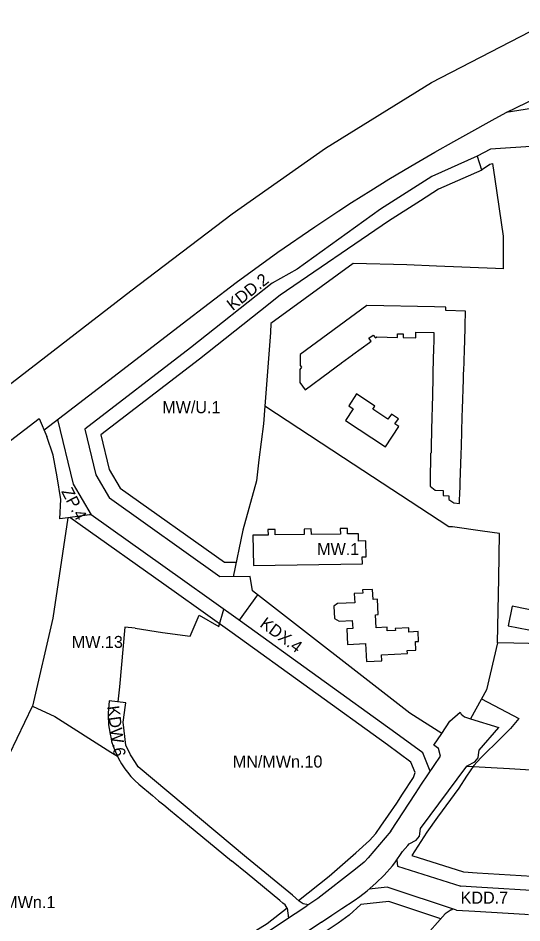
# Model space of a CAD drawing. Extents: x 7427074 to 7428708, y 5545888 to 5547145.
# Drawn here: x 7427353.4 to 7427562.4, y 5546349.6 to 5546725 of the extents above; entities that cross this region are included whole.
import ezdxf

# ---------------------------------------------------------------- set-up
doc = ezdxf.new("R2010")
doc.units = 0
for name, color, linetype in [('linie_rozgraniczajace', 7, 'Continuous'), ('linie_zabudowy_nieprzekraczalne', 7, 'Continuous'), ('linie_zabudowy_obowiazujace', 7, 'Continuous'), ('oznaczenia_przeznaczen', 7, 'Continuous')]:
    doc.layers.add(name, color=color, linetype=linetype)

msp = doc.modelspace()

# ---------------------------------------------------------------- linework, layer by layer
at = {"layer": 'linie_rozgraniczajace'}
for p, q in [((7427245.64, 5546492.63), (7427400.2, 5546611.86)), ((7427362.2, 5546558.93), (7427365.35, 5546551.44)), ((7427369.81, 5546558.47), (7427376.26, 5546531.66)), ((7427367.91, 5546543.69), (7427365.35, 5546551.44)), ((7427385.64, 5546535.45), (7427391.29, 5546525.85)), ((7427376.26, 5546531.66), (7427383.75, 5546518.94)), ((7427437.14, 5546493.18), (7427391.29, 5546525.85)), ((7427421.58, 5546491.99), (7427383.75, 5546518.94)), ((7427445.72, 5546474.79), (7427421.58, 5546491.99)), ((7427452.66, 5546485.74), (7427445.15, 5546475.2)), ((7427436.65, 5546472.62), (7427438.79, 5546479.73)), ((7427547.71, 5546446.24), (7427541.02, 5546434.22)), ((7427391.87, 5546420.47), (7427394.65, 5546418.71)), ((7427539.52, 5546414.55), (7427557.29, 5546413.6)), ((7427510.46, 5546375.65), (7427510.8, 5546373.1)), ((7427510.8, 5546373.1), (7427537.12, 5546364.79)), ((7427506.51, 5546364.47), (7427498.99, 5546363.62)), ((7427535.29, 5546354.89), (7427506.51, 5546364.47)), ((7427533.07, 5546355.02), (7427533.68, 5546355.42))]:
    msp.add_line(p, q, dxfattribs=at)
for points in [[(7427400.2, 5546611.86), (7427442.19, 5546643.82), (7427480.94, 5546671.03), (7427524.86, 5546698.24), (7427615.03, 5546744.99), (7427747.54, 5546812.47), (7427897.12, 5546887.45), (7428084.42, 5546980.69), (7428179.45, 5547028.08)], [(7427364.2, 5546554.17), (7427395.05, 5546577.83), (7427421.52, 5546598.13), (7427443.89, 5546615.25), (7427461.19, 5546627.88), (7427476.45, 5546638.44), (7427486.49, 5546645.1), (7427491.66, 5546648.44), (7427499.68, 5546653.51), (7427507.23, 5546658.17), (7427516.35, 5546663.63), (7427526.34, 5546669.42), (7427534.09, 5546673.78), (7427540.36, 5546677.22), (7427550.02, 5546682.6), (7427555.89, 5546685.9), (7427594.96, 5546704.86), (7427638.36, 5546720.62)], [(7427655.48, 5546683.03), (7427641.71, 5546683.78), (7427625.07, 5546685.04), (7427596.01, 5546686.32), (7427586.83, 5546686.79), (7427569.02, 5546687.86), (7427555.86, 5546685.88)], [(7427670.02, 5546665.3), (7427656.69, 5546667.04), (7427641.81, 5546667.88), (7427623.85, 5546668.9), (7427585.97, 5546670.99), (7427568.18, 5546671.93), (7427549.37, 5546670.57), (7427543.89, 5546667.66), (7427525, 5546659.31), (7427503.72, 5546645.77), (7427469.2, 5546620.79), (7427458.78, 5546615.05), (7427424.98, 5546588.18), (7427381.06, 5546554.49)], [(7427543.89, 5546667.66), (7427545.7, 5546661.99), (7427549.06, 5546664.43), (7427550.23, 5546664.64), (7427551.17, 5546658.23), (7427554.64, 5546634.49), (7427554.66, 5546620.99), (7427551.42, 5546621.12), (7427526.94, 5546622.11), (7427514.73, 5546622.57), (7427492.47, 5546623.2), (7427472.43, 5546608.61), (7427458.25, 5546598.27), (7427458.14, 5546594.5), (7427455.74, 5546564.02)], [(7427552.3, 5546465.76), (7427552.8, 5546492.67), (7427553.14, 5546511.14), (7427546.01, 5546512.12), (7427533.67, 5546513.88), (7427532.08, 5546513.86), (7427488.33, 5546542.61), (7427455.74, 5546564.02), (7427455.16, 5546556.61), (7427453.34, 5546541.67), (7427452.3, 5546532.98)], [(7427202.76, 5546436.65), (7427362.2, 5546558.93)], [(7427381.06, 5546554.49), (7427385.64, 5546535.45)], [(7427374, 5546517.72), (7427370.69, 5546517.27), (7427371.12, 5546525.28), (7427369.63, 5546534.69), (7427367.91, 5546543.69)], [(7427452.3, 5546532.98), (7427446.7, 5546512.58), (7427442.65, 5546493.23)], [(7427374, 5546517.72), (7427367.84, 5546476.07), (7427359.35, 5546439.56)], [(7427383.75, 5546518.94), (7427382.98, 5546518.97), (7427374, 5546517.72)], [(7427529.12, 5546428.2), (7427515.88, 5546436.56), (7427450.6, 5546487.35), (7427449.63, 5546493.29), (7427437.14, 5546493.18)], [(7427401.93, 5546471.81), (7427413.29, 5546470.12), (7427424.76, 5546468.55), (7427428.56, 5546477.33), (7427436.65, 5546472.62)], [(7427524.4, 5546412.55), (7427521.25, 5546420.11), (7427510.14, 5546428.36), (7427445.72, 5546474.79)], [(7427401.93, 5546471.81), (7427397.76, 5546472.31), (7427395.44, 5546447.54), (7427394.79, 5546441.29)], [(7427571.25, 5546465.36), (7427558.99, 5546465.62), (7427552.3, 5546465.76), (7427547.71, 5546446.24)], [(7427346.74, 5546412.98), (7427359.35, 5546439.56)], [(7427359.35, 5546439.56), (7427368.72, 5546435.2), (7427391.87, 5546420.47)], [(7427473.91, 5546357.13), (7427471.62, 5546357.48), (7427470.07, 5546358.66), (7427467.2, 5546361.06), (7427448.12, 5546376.67), (7427403.29, 5546414.31), (7427402.06, 5546416.09), (7427399.99, 5546419.3), (7427398.11, 5546423.3), (7427397.05, 5546432.84), (7427397.97, 5546439.96), (7427398.11, 5546440.94), (7427391.2, 5546441.66), (7427390.81, 5546436.61), (7427390.81, 5546434.76), (7427390.9, 5546432.78), (7427390.99, 5546431.77), (7427391.15, 5546430.3), (7427391.55, 5546427.84), (7427391.99, 5546425.97), (7427392.23, 5546424.91), (7427392.87, 5546422.98), (7427393.82, 5546420.51), (7427395.08, 5546417.78), (7427396.36, 5546415.65), (7427397.71, 5546413.56), (7427398.76, 5546412.13), (7427400.24, 5546410.37), (7427401.81, 5546408.68), (7427403.48, 5546407.09), (7427405.13, 5546405.71), (7427407.48, 5546403.76), (7427409.11, 5546402.39), (7427411.65, 5546400.27), (7427413.9, 5546398.52), (7427416.68, 5546396.21), (7427421.32, 5546392.37), (7427423.74, 5546390.48), (7427441.92, 5546375.34)], [(7427508.07, 5546387.66), (7427518.26, 5546403.28), (7427520.79, 5546407.15), (7427528.57, 5546418.77), (7427527.79, 5546421.99), (7427525.86, 5546423.31), (7427529.12, 5546428.2), (7427532.56, 5546433.34), (7427536.76, 5546437.06), (7427537.26, 5546436.2), (7427538.61, 5546435.05), (7427541.02, 5546434.22), (7427552.88, 5546430.65)], [(7427479.26, 5546349.84), (7427483.58, 5546352.73), (7427487.77, 5546355.52), (7427492.82, 5546358.9), (7427495.14, 5546360.55), (7427498.22, 5546362.95), (7427501.78, 5546366.05), (7427505.2, 5546369.35), (7427508.71, 5546373.21), (7427509.7, 5546374.51), (7427512.82, 5546379.21), (7427515.11, 5546381.76), (7427515.6, 5546382.42), (7427518.55, 5546383.91), (7427519.86, 5546385.58), (7427520.33, 5546388.79), (7427539.52, 5546414.55), (7427539.67, 5546414.74), (7427542.87, 5546416.35), (7427544.22, 5546418.08), (7427544.4, 5546419.3), (7427544.68, 5546421.22), (7427552.88, 5546430.65)], [(7427557.29, 5546413.6), (7427568.29, 5546413.01), (7427576.26, 5546387.77)], [(7427508.07, 5546387.66), (7427498.56, 5546376.59), (7427497.07, 5546374.91), (7427496.93, 5546374.74), (7427493.38, 5546371.94), (7427477.78, 5546359.68), (7427473.12, 5546356.61)], [(7427465.07, 5546355.74), (7427464.67, 5546356.41), (7427464.16, 5546357.01), (7427463.29, 5546357.8), (7427461.95, 5546358.91), (7427448.41, 5546370.12), (7427441.92, 5546375.34)], [(7427585.66, 5546361.85), (7427570.85, 5546362.75), (7427543.53, 5546364.4), (7427537.12, 5546364.79)], [(7427337.22, 5546278.25), (7427357.81, 5546290.12), (7427362.65, 5546292.17), (7427367.93, 5546295.03), (7427371.59, 5546297.02), (7427376.72, 5546299.98), (7427389.23, 5546307.22), (7427411.07, 5546319.08), (7427416.4, 5546321.96), (7427416.99, 5546320.6), (7427421.81, 5546323.13), (7427428.21, 5546326.84), (7427431.47, 5546329), (7427434.68, 5546331.13), (7427468.39, 5546353.49), (7427473.12, 5546356.61)], [(7427465.07, 5546355.74), (7427465.52, 5546351.58)], [(7427533.07, 5546355.02), (7427530.57, 5546353.37), (7427524.16, 5546346.19), (7427522.69, 5546344.23), (7427520.72, 5546340.78), (7427518.78, 5546337.59), (7427516.03, 5546333.03), (7427513.63, 5546329.06), (7427512.52, 5546326.87), (7427512.14, 5546326.11), (7427511.99, 5546325.8), (7427507.15, 5546316.17), (7427498.79, 5546300.65), (7427495.71, 5546294.66), (7427491.99, 5546288.77), (7427487.56, 5546281.59), (7427485.5, 5546278.63), (7427480.53, 5546273.21), (7427478.17, 5546270.58), (7427477.6, 5546269.37)], [(7427535.29, 5546354.89), (7427542.92, 5546354.42), (7427563.55, 5546353.18), (7427565.07, 5546353.09)], [(7427479.26, 5546349.84), (7427467.13, 5546341.73), (7427458.44, 5546335.98), (7427442.11, 5546325.17), (7427425.1, 5546314.77), (7427419.81, 5546311.95), (7427414.6, 5546309.15), (7427402.89, 5546302.98), (7427380.2, 5546291.01), (7427369.27, 5546285.25), (7427354.06, 5546276.83), (7427340.36, 5546269.25), (7427329.45, 5546262.24), (7427324.29, 5546258.02), (7427314.5, 5546248.22), (7427302.27, 5546235.33)]]:
    msp.add_lwpolyline(points, dxfattribs=at)
at = {"layer": 'linie_zabudowy_nieprzekraczalne'}
for p, q in [((7427545.65, 5546442.54), (7427561.18, 5546434.41)), ((7427517.43, 5546409.94), (7427518.11, 5546412.05)), ((7427507.21, 5546358.51), (7427495.65, 5546357.21)), ((7427528.75, 5546351.33), (7427507.21, 5546358.51))]:
    msp.add_line(p, q, dxfattribs=at)
for points in [[(7427545.72, 5546661.91), (7427527.84, 5546654.01), (7427520.37, 5546649.25)], [(7427520.37, 5546649.25), (7427507.09, 5546640.8), (7427462.12, 5546610.04), (7427454.02, 5546603.6)], [(7427387.8, 5546552.1), (7427391.26, 5546537.72), (7427395.81, 5546529.99), (7427439.04, 5546499.2), (7427443.91, 5546499.24)], [(7427518.11, 5546412.05), (7427516.35, 5546416.28), (7427506.59, 5546423.52), (7427442.23, 5546469.92), (7427418.1, 5546487.1), (7427374.94, 5546517.85)], [(7427561.18, 5546434.41), (7427557.61, 5546430.3), (7427553.76, 5546426.43), (7427545.39, 5546418.04), (7427542.51, 5546414.93), (7427539.47, 5546410.51), (7427536.21, 5546405.47), (7427527.39, 5546393.51), (7427522.96, 5546387.21), (7427516.68, 5546377.54), (7427538.22, 5546370.74), (7427543.89, 5546370.39), (7427571.22, 5546368.74), (7427586.1, 5546367.84), (7427620.52, 5546364.9)], [(7427499.2, 5546383.71), (7427501.75, 5546386.74), (7427503.82, 5546389.69), (7427507.1, 5546394.26), (7427510.56, 5546399.25), (7427512.91, 5546402.93), (7427517.43, 5546409.94)], [(7427469.76, 5546358.91), (7427482.44, 5546368.99), (7427493.51, 5546378.63), (7427499.2, 5546383.71)], [(7427495.65, 5546357.21), (7427490.69, 5546352.83), (7427486.19, 5546349.49), (7427480.4, 5546345.55), (7427466.21, 5546335.53), (7427452.71, 5546325.77), (7427445.38, 5546321.77), (7427439.81, 5546318.7), (7427418.08, 5546306.01), (7427404.24, 5546299.5), (7427392.77, 5546293.83), (7427373.57, 5546284.17), (7427366.91, 5546280.83), (7427354.99, 5546274.14)], [(7427257.14, 5546195.43), (7427285.02, 5546234.34), (7427290.57, 5546240.98), (7427293.76, 5546244.92), (7427305.32, 5546258.92), (7427313.52, 5546269.3), (7427316.86, 5546272.22), (7427340.92, 5546285.7), (7427355.54, 5546293.85), (7427357.88, 5546295.45), (7427365.28, 5546299.95), (7427382.65, 5546309.18), (7427384.23, 5546310.01), (7427404.8, 5546319.28), (7427408.61, 5546321.5), (7427431.21, 5546333.63), (7427456.78, 5546349.28), (7427464.99, 5546355.87)]]:
    msp.add_lwpolyline(points, dxfattribs=at)
at = {"layer": 'linie_zabudowy_obowiazujace'}
for points in [[(7427526.16, 5546605.2), (7427498.01, 5546605.73), (7427470.47, 5546585.4), (7427470.39, 5546580.9), (7427471.03, 5546580.24), (7427470.35, 5546579.23), (7427470.25, 5546573.8), (7427472.48, 5546570.79), (7427482.57, 5546578.24), (7427482.77, 5546578.39), (7427487.4, 5546581.81), (7427487.6, 5546581.95), (7427492.09, 5546585.27), (7427492.29, 5546585.42), (7427499.13, 5546590.47), (7427499.33, 5546590.61), (7427499.81, 5546590.97), (7427498.92, 5546592.18), (7427500.73, 5546593.51), (7427501.62, 5546592.31), (7427502.23, 5546592.74), (7427510.73, 5546592.48), (7427510.75, 5546593.98), (7427513.1, 5546593.94), (7427513.08, 5546592.44), (7427518.33, 5546592.36), (7427518.36, 5546594.71), (7427525.9, 5546594.57)], [(7427525.9, 5546594.57), (7427525.81, 5546590.74), (7427525.75, 5546588.2), (7427525.5, 5546578.08), (7427525.49, 5546577.83), (7427525.44, 5546575.59), (7427525.43, 5546575.34), (7427525.14, 5546563.09), (7427525.13, 5546562.84), (7427525.06, 5546560.06), (7427525.05, 5546559.81), (7427524.76, 5546547.58), (7427524.75, 5546547.33), (7427524.69, 5546544.61), (7427524.46, 5546544.35), (7427524.4, 5546532.6), (7427524.39, 5546532.34), (7427524.35, 5546530.83), (7427526.38, 5546529.13), (7427529.77, 5546529.05), (7427529.72, 5546526.87), (7427532.08, 5546526.81), (7427532.04, 5546525.31), (7427534.12, 5546523.86), (7427536.56, 5546523.65), (7427536.71, 5546529.09), (7427536.72, 5546529.35), (7427536.8, 5546532.1), (7427536.81, 5546532.35), (7427537.18, 5546544.09), (7427537.19, 5546544.34), (7427537.28, 5546547.1), (7427537.28, 5546547.35), (7427537.67, 5546559.57), (7427537.67, 5546559.82), (7427537.76, 5546562.58), (7427537.77, 5546562.83), (7427538.15, 5546575.07), (7427538.16, 5546575.32), (7427538.23, 5546578.1), (7427538.26, 5546578.33), (7427538.55, 5546587.29), (7427538.56, 5546587.59), (7427538.57, 5546587.86), (7427538.65, 5546590.56), (7427538.66, 5546590.81), (7427538.85, 5546597.09), (7427538.86, 5546597.34), (7427539.05, 5546603.43), (7427530.87, 5546603.69), (7427530.89, 5546605.11), (7427526.16, 5546605.2)], [(7427454.02, 5546603.6), (7427428.67, 5546583.45), (7427387.8, 5546552.1)]]:
    msp.add_lwpolyline(points, dxfattribs=at)
for points in [[(7427490.54, 5546564.19), (7427492.45, 5546562.91), (7427489.18, 5546558), (7427505.78, 5546547.18), (7427511.36, 5546555.49), (7427509.7, 5546556.61), (7427511.14, 5546558.77), (7427508.24, 5546560.71), (7427506.79, 5546558.56), (7427500.57, 5546562.74), (7427501.4, 5546563.99), (7427493.8, 5546569.08)], [(7427451.04, 5546497.91), (7427496.21, 5546498.55), (7427496.14, 5546501.51), (7427497.77, 5546501.53), (7427497.63, 5546508.06), (7427494.67, 5546508.04), (7427494.65, 5546511.03), (7427490.09, 5546510.98), (7427490.05, 5546513.25), (7427487.05, 5546513.22), (7427487.09, 5546510.93), (7427475.07, 5546510.76), (7427475.04, 5546513.04), (7427472.07, 5546513.01), (7427472.1, 5546510.71), (7427460.1, 5546510.55), (7427460.07, 5546512.83), (7427457.06, 5546512.79), (7427457.09, 5546510.5), (7427450.83, 5546510.41)], [(7427502.71, 5546477.51), (7427502.44, 5546483.9), (7427500.66, 5546483.82), (7427500.49, 5546487.94), (7427496.31, 5546487.76), (7427496.37, 5546486.35), (7427492.88, 5546486.21), (7427493.04, 5546482.4), (7427485.93, 5546482.1), (7427484.34, 5546481.02), (7427484.62, 5546475.91), (7427486.59, 5546474.82), (7427492.04, 5546475.12), (7427492.22, 5546471.77), (7427489.72, 5546471.64), (7427490.08, 5546465.07), (7427497.49, 5546465.48), (7427497.89, 5546458.03), (7427504.34, 5546458.37), (7427504.21, 5546460.81), (7427514.88, 5546461.39), (7427514.82, 5546462.57), (7427518.43, 5546462.77), (7427518.23, 5546466.31), (7427519.52, 5546466.38), (7427519.3, 5546470.46), (7427515.55, 5546470.26), (7427515.45, 5546472.04), (7427509.85, 5546471.74), (7427509.9, 5546470.91), (7427506.54, 5546470.73), (7427506.46, 5546472.32), (7427501.92, 5546472.07), (7427501.63, 5546477.45)], [(7427558.33, 5546480.99), (7427556.71, 5546472.91), (7427569.59, 5546470.33), (7427571.21, 5546478.41)]]:
    msp.add_lwpolyline(points, close=True, dxfattribs=at)

# ---------------------------------------------------------------- texts
at = {"layer": 'oznaczenia_przeznaczen'}
for s, rotation, p in [('KDD.2', 38.381, (7427442.45, 5546603.36)), ('ZP.4', 297.6373, (7427371.2, 5546528.63)), ('KDX.4', 323.7056, (7427453.34, 5546472.78)), ('KDW.6', 277.6308, (7427390.37, 5546439.37))]:
    msp.add_text(s, height=5, rotation=rotation, dxfattribs=at).set_placement(p)
for s, p in [('MW/U.1', (7427413.22, 5546561.08)), ('MW.1', (7427477.46, 5546502.18)), ('MW.13', (7427375.7, 5546463.67)), ('MN/MWn.10', (7427442.49, 5546414.04)), ('MN/MWn.1', (7427335.44, 5546355.7)), ('KDD.7', (7427536.98, 5546357.56))]:
    msp.add_text(s, height=5, dxfattribs=at).set_placement(p)

doc.saveas('drawing.dxf')
